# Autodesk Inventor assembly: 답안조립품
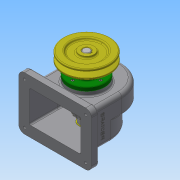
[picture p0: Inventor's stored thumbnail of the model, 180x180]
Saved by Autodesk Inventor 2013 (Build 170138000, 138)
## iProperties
Created: 2017-11
Part Number: 답안조립품
Document SubType Name: Assembly
Designer: Administrator
Author: Administrator
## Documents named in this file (14)
- C:\Users\Administrator\Desktop\471108V1014\답안조립품.iam
- C:\Users\Administrator\Desktop\471108V1014\본체.ipt
- C:\Users\Administrator\Desktop\471108V1014\V-벨트풀리.ipt
- C:\Users\Administrator\Desktop\471108V1014\뒤커버.ipt
- C:\Users\Administrator\Desktop\471108V1014\멈춤나사 - M4 x 10.ipt
- 멈춤나사 - M4 x 10.ipt
- C:\Users\Administrator\Desktop\471108V1014\베어링 6002.ipt
- C:\Users\Administrator\Desktop\471108V1014\볼트 M3 x 8.ipt
- C:\Users\Administrator\Desktop\471108V1014\스퍼기어.ipt
- C:\Users\Administrator\Desktop\471108V1014\앞커버.ipt
- C:\Users\Administrator\Desktop\471108V1014\오일 실 15 30 7.ipt
- C:\Users\Administrator\Desktop\471108V1014\축.ipt
- C:\Users\Administrator\Desktop\471108V1014\키 - 5 x 5 x 18.ipt
- C:\Users\Administrator\Desktop\471108V1014\키 - 6 x 6 x 22.ipt
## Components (1 placed, 1 different names)
1. V-벨트풀리:1
